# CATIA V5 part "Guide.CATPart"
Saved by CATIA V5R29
Part number: Guide
Source: Unknown
Bounding box of the stored display mesh (mm): x 0 to 200, y -20 to 20, z 730 to 1000
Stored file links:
  C:\Users\Administrator\Desktop\프로젝트\Boxfold\Guide\Guide.CATPart
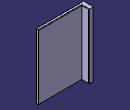
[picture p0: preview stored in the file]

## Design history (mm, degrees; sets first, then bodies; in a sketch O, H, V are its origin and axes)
Set1
  Sketch1 on face of Solid1, origin (0, 0, 0), H (0, 0, 1), V (0, 1, 0)
    line L1 (190, -20) -> (-1000, -20)
    line L2 (-1000, -20) -> (-1000, 20)
    line L3 (-1000, 20) -> (190, 20)
    line L4 (190, 20) -> (190, -20)
    reference intersected line E1 through (280, 0) direction (0, 1) from face of DatumSurface1
    reference intersected line E2 through (0, 20) direction (1, 0) from face of Solid1
    reference intersected line E3 through (0, -20) direction (-1, 0) from face of Solid1
    reference intersected line E4 through (-1000, 0) direction (0, 1) from face of Solid1
    distance L4 E1 = 90
    horizontal: L1 H, L3 H
    vertical: L2 V, L4 V
    coincidence: L3 E2, L1 E3, E4 L2
  DatumSurface1
Body1 (main body)
  Solid1 "PartBody": solid without history
  Pocket1: profile Sketch1, direction (1, 0, 0), through (limit type 6)
  DatumSurface2 to DatumSurface4
  Sketch2 on face of Solid1, origin (20, 0, 0), H (0, 0, -1), V (0, 1, 0)
    line L1 (-730, 25) -> (-190, 25)
    line L2 (-190, 25) -> (-190, -72)
    line L3 (-190, -72) -> (-730, -72)
    line L4 (-730, -72) -> (-730, 25)
    reference intersected line E1 through (-820, 0) direction (0, -1) from face of DatumSurface2
    reference intersected line E2 through (0, -72) direction (1, 0) from face of DatumSurface3
    reference intersected line E3 (-190, -18) -> (-190, 18) from face of Pocket1 from Sketch1.L4
    reference intersected line E4 through (0, 25) direction (1, 0) from face of DatumSurface4
    distance L4 E1 = 90
    horizontal: L1 H, L3 H
    vertical: L2 V, L4 V
    coincidence: L3 E2, L2 E3, L1 E4
  Pocket2: profile Sketch2, direction (-1, 0, 0), through (limit type 3)
  Fillet1: radius 2, on edge [face of Solid1 | face of Pocket2 from Sketch2.L4]
  Sketch3 on face of Solid1, origin (20, 0, 0), H (0, 0, -1), V (0, 1, 0)
    line L1 (-1000, -10) -> (-730, -10)
    line L2 (-730, -10) -> (-730, -20)
    line L3 (-730, -20) -> (-1000, -20)
    line L4 (-1000, -20) -> (-1000, -10)
    reference projected line E1 (-998, -20) -> (998, -20) from edge [face of Solid1 | face of Solid1]
    reference intersected line E2 (-730, -18) -> (-730, 18) from face of Pocket2 from Sketch2.L4
    reference intersected line E3 through (-1000, 0) direction (0, 1) from face of Solid1
    distance L1 L3 = 10
    horizontal: L1 H, L3 H
    vertical: L2 V, L4 V
    coincidence: L3 E1, L2 E2, L4 E3
  Pad1: profile Sketch3, direction (1, 0, 0), length 180, opposite side length 20
  Fillet2: radius 2, on edge [face of Pad1 | face of Pad1] (x2); edge [face of Pad1 | face of Pad1 from Sketch3.L1]; edge [face of Pad1 from Sketch3.L1 | face of Pad1]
